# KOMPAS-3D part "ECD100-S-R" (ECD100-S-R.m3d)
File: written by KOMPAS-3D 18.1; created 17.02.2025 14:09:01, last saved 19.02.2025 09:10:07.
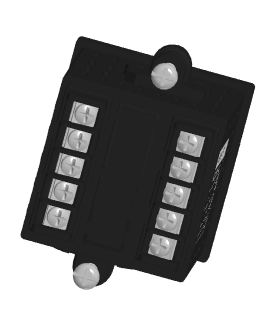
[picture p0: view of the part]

Document properties: Полное имя файла: Z:\Элхарт\БД\3D модели приборов для сайта\ECD100-S-R\ECD100-S-R.m3d

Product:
- Part/product: ECD100-S-R
    Масса: 0.394329
  - Body: Тело 10
      Масса: 0.00304902
  - Body: Тело 9
      Масса: 0.000835177
  - Body: Тело 7
      Масса: 0.0471975
  - Body: Тело 6
      Масса: 0.0471975
  - Body: Тело 5
      Масса: 0.0239858
  - Body: Тело 4
      Масса: 0.0239858
  - Body: Тело 3
      Масса: 0.180561
  - Body: Тело 2
      Масса: 0.000834949
  - Body: Тело 1
      Масса: 0.0666826

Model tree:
1. Операция без истории:1
2. Операция без истории:2
3. Операция без истории:3
4. Операция без истории:4
5. Операция без истории:5
6. Операция без истории:6
7. Операция без истории:7
8. Операция без истории:9
9. Операция без истории:10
